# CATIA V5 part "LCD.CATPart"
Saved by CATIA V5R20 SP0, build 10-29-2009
Part number: camera
Bounding box of the stored display mesh (mm): x -13 to 1, y 0 to 200, z 0 to 40
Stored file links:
  C:\Users\bensf\Desktop\bouthaina\LCD.CATPart
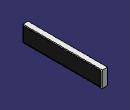
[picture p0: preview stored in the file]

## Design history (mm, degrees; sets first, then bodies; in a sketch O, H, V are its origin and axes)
Body1 (main body)
  Sketch1 on yz-plane, origin (0, 0, 0), H (0, 1, 0), V (0, 0, 1)
    line L1 (0, 0) -> (200, 0)
    line L2 (200, 0) -> (200, 40)
    line L3 (200, 40) -> (0, 40)
    line L4 (0, 40) -> (0, 0)
    length L1 = 200
    length L2 = 40
    horizontal: L1 H, L3 H
    vertical: L2 V, L4 V
  Sketch2 on zx-plane, origin (0, 0, 0), H (-1, 0, 0), V (0, 0, 1)
    line L1 (0, 0) -> (13, 0)
    length L1 = 13
    horizontal: L1 H
  Rib1: profile Sketch1, centre curve Sketch2
  Sketch3 on face of Rib1, origin (0, 0, 0), H (0, 1, 0), V (0, 0, 1)
    line L1 (2.3918, 37.3424) -> (197.1117, 37.3424)
    line L2 (197.1117, 37.3424) -> (197.1117, 2.6215)
    line L3 (197.1117, 2.6215) -> (2.3918, 2.6215)
    line L4 (2.3918, 2.6215) -> (2.3918, 37.3424)
    horizontal: L1 H, L3 H
    vertical: L2 V, L4 V
  Pad1: profile Sketch3, direction (1, 0, 0), length 1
